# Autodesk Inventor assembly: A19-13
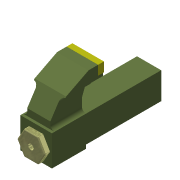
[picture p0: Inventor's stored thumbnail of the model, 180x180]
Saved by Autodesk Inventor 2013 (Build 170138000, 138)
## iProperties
Created: 2008-07
Part Number: A19-13
Document SubType Name: Assembly
Designer: y-shimohigashi
Stock Number: A19-13
Author: y-shimohigashi
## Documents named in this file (5)
- C:\Users\t-komatsu\Desktop\新しいフォルダー\Inventor2013基礎コース\練習問題-19\A19-13.iam
- C:\Users\t-komatsu\Desktop\新しいフォルダー\Inventor2013基礎コース\練習問題-19\P19-4締付板.ipt
- C:\Users\t-komatsu\Desktop\新しいフォルダー\Inventor2013基礎コース\練習問題-19\P19-6締付ネジ押え板.ipt
- C:\Users\t-komatsu\Desktop\新しいフォルダー\Inventor2013基礎コース\練習問題-19\P19-3締付金具.ipt
- C:\Users\t-komatsu\Desktop\新しいフォルダー\Inventor2013基礎コース\練習問題-19\P19-11ボルト.ipt
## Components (5 placed, 4 different names)
1. P19-4締付板:1 — 挿入:3, 挿入:4
2. P19-6締付ネジ押え板:1
3. P19-3締付金具:1
4. P19-11ボルト:1 — 挿入:4
5. P19-11ボルト:2 — 挿入:3
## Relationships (2: Insert 2)
- 挿入:3 [Insert]: P19-4締付板:1 ↔ P19-11ボルト:2
- 挿入:4 [Insert]: P19-4締付板:1 ↔ P19-11ボルト:1
